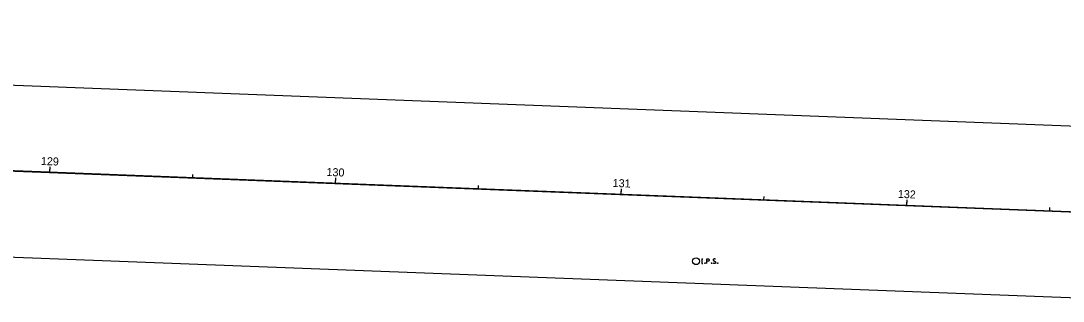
# Model space of a CAD drawing. Extents: x 2003596 to 2006888, y 571866 to 574416.
# Drawn here: x 2005624 to 2005988.6, y 572567.3 to 572665.2 of the extents above; entities that cross this region are included whole.
import ezdxf

# ---------------------------------------------------------------- set-up
doc = ezdxf.new("R2010")
doc.units = 0
for name, color, linetype in [('GE_X_Alignment', 7, 'Continuous'), ('GE_X_Alignment_1000_Stations', 7, 'Continuous'), ('GE_X_Alignment_100_Stations', 7, 'Continuous'), ('GE_X_Alignment_500_Stations', 7, 'Continuous'), ('RW_X_CL', 7, 'Continuous'), ('RW_X_Esmt_SH', 7, 'Continuous'), ('SC_Scratch10', 7, 'Continuous'), ('SV_P_Mon_Cells_Set', 7, 'Continuous')]:
    doc.layers.add(name, color=color, linetype=linetype)

msp = doc.modelspace()

# ---------------------------------------------------------------- linework, layer by layer
at = {"layer": 'GE_X_Alignment'}
msp.add_line((2005031.48, 572635.32), (2006023.62, 572597.25), dxfattribs=at)
at = {"layer": 'GE_X_Alignment_1000_Stations'}
msp.add_line((2005734.03, 572608.36), (2005734.11, 572610.36), dxfattribs=at)
at = {"layer": 'GE_X_Alignment_100_Stations'}
for p, q in [((2005634.11, 572612.2), (2005634.18, 572614.19)), ((2005684.07, 572610.28), (2005684.12, 572611.48)), ((2005734.03, 572608.36), (2005734.11, 572610.36)), ((2005784, 572606.44), (2005784.04, 572607.64)), ((2005833.96, 572604.53), (2005834.04, 572606.53)), ((2005883.92, 572602.61), (2005883.97, 572603.81)), ((2005933.89, 572600.69), (2005933.96, 572602.69)), ((2005983.85, 572598.78), (2005983.9, 572599.98))]:
    msp.add_line(p, q, dxfattribs=at)
at = {"layer": 'GE_X_Alignment_500_Stations'}
for p, q in [((2005634.11, 572612.2), (2005634.15, 572613.4)), ((2005734.03, 572608.36), (2005734.11, 572610.36)), ((2005833.96, 572604.53), (2005834.01, 572605.73)), ((2005933.89, 572600.69), (2005933.93, 572601.89))]:
    msp.add_line(p, q, dxfattribs=at)
at = {"layer": 'RW_X_CL'}
msp.add_line((2006023.62, 572597.25), (2005031.48, 572635.32), dxfattribs=at)
at = {"layer": 'RW_X_Esmt_SH'}
for p, q in [((2005034.78, 572665.22), (2006024.45, 572627.24)), ((2005028.18, 572605.42), (2006022.8, 572567.26))]:
    msp.add_line(p, q, dxfattribs=at)
at = {"layer": 'SC_Scratch10'}
msp.add_line((2006023.71, 572597.25), (2005465.42, 572618.88), dxfattribs=at)
at = {"layer": 'SV_P_Mon_Cells_Set'}
for points in [[(2005862.17, 572582.02), (2005862.52, 572582.02)], [(2005862.34, 572580.42), (2005862.34, 572582.02)], [(2005863.91, 572580.42), (2005863.91, 572582.02), (2005864.44, 572582.02), (2005864.49, 572582), (2005864.57, 572581.98), (2005864.6, 572581.95), (2005864.64, 572581.93), (2005864.68, 572581.86), (2005864.71, 572581.8), (2005864.74, 572581.7), (2005864.74, 572581.55), (2005864.72, 572581.5), (2005864.7, 572581.42), (2005864.66, 572581.33), (2005864.61, 572581.3), (2005864.58, 572581.27), (2005864.53, 572581.25), (2005864.44, 572581.23), (2005863.91, 572581.23)], [(2005866.92, 572581.9), (2005866.9, 572581.93), (2005866.86, 572581.95), (2005866.76, 572581.99), (2005866.64, 572582.02), (2005866.55, 572582.02), (2005866.52, 572582.02), (2005866.38, 572581.98), (2005866.26, 572581.9), (2005866.18, 572581.8), (2005866.16, 572581.7), (2005866.16, 572581.62), (2005866.18, 572581.52), (2005866.27, 572581.44), (2005866.87, 572581.06), (2005866.93, 572581.01), (2005866.95, 572580.96), (2005866.97, 572580.88), (2005866.97, 572580.81), (2005866.96, 572580.73), (2005866.95, 572580.68), (2005866.93, 572580.62), (2005866.91, 572580.57), (2005866.88, 572580.53), (2005866.85, 572580.49), (2005866.82, 572580.47), (2005866.77, 572580.44), (2005866.74, 572580.43), (2005866.64, 572580.42), (2005866.49, 572580.42), (2005866.39, 572580.44), (2005866.25, 572580.53), (2005866.16, 572580.6)], [(2005862.17, 572580.42), (2005862.52, 572580.42)], [(2005863.3, 572580.63), (2005863.36, 572580.63), (2005863.39, 572580.6), (2005863.42, 572580.55), (2005863.42, 572580.49), (2005863.39, 572580.44), (2005863.36, 572580.42), (2005863.3, 572580.42), (2005863.27, 572580.44), (2005863.24, 572580.49), (2005863.24, 572580.55), (2005863.27, 572580.6), (2005863.3, 572580.63)], [(2005865.55, 572580.63), (2005865.61, 572580.63), (2005865.64, 572580.6), (2005865.67, 572580.55), (2005865.67, 572580.49), (2005865.64, 572580.44), (2005865.61, 572580.42), (2005865.55, 572580.42), (2005865.52, 572580.44), (2005865.48, 572580.49), (2005865.48, 572580.55), (2005865.52, 572580.6), (2005865.55, 572580.63)], [(2005867.73, 572580.63), (2005867.79, 572580.63), (2005867.82, 572580.6), (2005867.85, 572580.55), (2005867.85, 572580.49), (2005867.82, 572580.44), (2005867.79, 572580.42), (2005867.73, 572580.42), (2005867.7, 572580.44), (2005867.67, 572580.49), (2005867.67, 572580.55), (2005867.7, 572580.6), (2005867.73, 572580.63)]]:
    msp.add_lwpolyline(points, dxfattribs=at)
msp.add_circle((2005860.15, 572581.21), 1.2, dxfattribs=at)

# ---------------------------------------------------------------- texts
at = {"layer": 'GE_X_Alignment_1000_Stations'}
msp.add_text('130', height=2.8, rotation=357.8026, dxfattribs=at).set_placement((2005730.85, 572611.03))
at = {"layer": 'GE_X_Alignment_100_Stations'}
for s, p in [('129', (2005630.95, 572614.87)), ('130', (2005730.85, 572611.03)), ('131', (2005830.95, 572607.19)), ('132', (2005930.71, 572603.36))]:
    msp.add_text(s, height=2.8, rotation=357.8026, dxfattribs=at).set_placement(p)
at = {"layer": 'GE_X_Alignment_500_Stations'}
msp.add_text('130', height=2.8, rotation=357.8026, dxfattribs=at).set_placement((2005730.85, 572611.03))

doc.saveas('drawing.dxf')
